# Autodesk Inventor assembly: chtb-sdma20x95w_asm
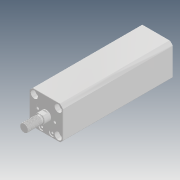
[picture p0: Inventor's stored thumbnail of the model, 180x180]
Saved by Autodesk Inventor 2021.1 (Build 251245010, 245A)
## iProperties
Company: Microsoft
Created: 2018-05
Part Number: chtb-sdma20x95w_asm
Description: STEP AP214
Document SubType Name: Assembly
Designer: user
Title: chtb-sdma20x95w_asm.STEP
Author: Windows
Revision Number: ÈÎºÎ
Sending System: SolidWorks 2015
Preprocessor: SwSTEP 2.0
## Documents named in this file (4)
- D:\Vault_2016\Projekty\Clamptek\Hydraulic\CHTB\CHTB-20\Inventor\CHTB-SDMA20x95W\chtb-sdma20x95w_asm.iam
- D:\Vault_2016\Projekty\Clamptek\Hydraulic\CHTB\CHTB-20\Inventor\CHTB-SDMA20x95W\CHTB-SDMA20X95NBT.ipt
- D:\Vault_2016\Projekty\Clamptek\Hydraulic\CHTB\CHTB-20\Inventor\CHTB-SDMA20x95W\CHTB-SDMA20X95WHSG.ipt
- D:\Vault_2016\Projekty\Clamptek\Hydraulic\CHTB\CHTB-20\Inventor\CHTB-SDMA20x95W\QG_3.ipt
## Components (3 placed, 3 different names)
1. CHTB-SDMA20X95NBT_1
2. CHTB-SDMA20X95WHSG_2
3. QG_3_3
